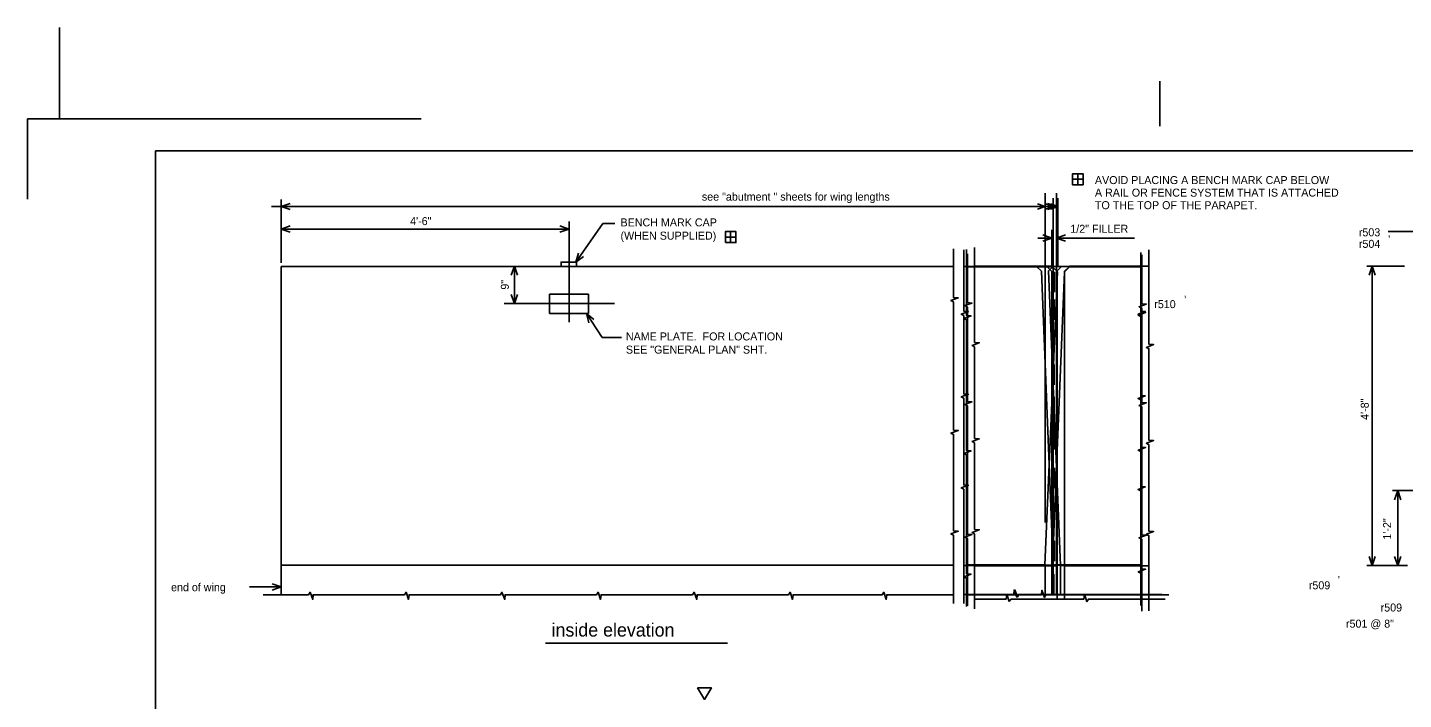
# Model space of a CAD drawing. Extents: x -81 to -44.8, y 85.9 to 111.1.
# Drawn here: x -79.8 to -58.31, y 100.62 to 111.12 of the extents above; entities that cross this region are included whole.
import ezdxf

# ---------------------------------------------------------------- set-up
doc = ezdxf.new("R2010")
doc.units = 0
for name, color, linetype in [('Default', 7, 'Continuous'), ('Level 1', 7, 'Continuous'), ('Level 12', 7, 'Continuous'), ('Level 13', 7, 'Continuous'), ('Level 14', 7, 'Continuous'), ('Level 15', 7, 'Continuous'), ('Level 16', 7, 'Continuous'), ('Level 2', 7, 'Continuous'), ('Level 37', 7, 'Continuous'), ('Level 5', 7, 'Continuous'), ('Level 9', 7, 'Continuous')]:
    doc.layers.add(name, color=color, linetype=linetype)

msp = doc.modelspace()

# ---------------------------------------------------------------- linework, layer by layer
at = {"layer": 'Default'}
msp.add_line((-57.819, 107.932), (-58.544, 107.932), dxfattribs=at)
at = {"layer": 'Level 1'}
for p, q in [((-73.646, 109.692), (-79.797, 109.692)), ((-79.797, 109.692), (-79.797, 108.439)), ((-77.797, 88.192), (-77.797, 109.192)), ((-46.422, 109.192), (-77.797, 109.192)), ((-58.289, 107.393), (-58.878, 107.393)), ((-58.795, 102.716), (-58.795, 107.393)), ((-57.703, 103.885), (-58.479, 103.885)), ((-58.395, 102.716), (-58.395, 103.885)), ((-58.243, 102.716), (-58.878, 102.716)), ((-58.475, 102.716), (-58.312, 102.716))]:
    msp.add_line(p, q, dxfattribs=at)
at = {"layer": 'Level 12'}
for p, q in [((-75.837, 108.323), (-63.724, 108.323)), ((-63.724, 107.33), (-63.724, 108.531)), ((-63.796, 107.363), (-63.796, 107.958)), ((-64.019, 107.83), (-63.796, 107.83)), ((-63.723, 107.83), (-62.508, 107.83)), ((-65.121, 107.387), (-63.876, 107.387)), ((-63.796, 107.307), (-63.876, 107.387)), ((-63.797, 107.308), (-63.797, 102.258)), ((-63.757, 107.3), (-63.757, 106.983)), ((-63.724, 107.306), (-63.724, 102.258)), ((-63.723, 107.307), (-63.647, 107.384)), ((-63.647, 107.387), (-62.405, 107.387)), ((-63.763, 106.868), (-63.763, 106.551)), ((-63.763, 106.362), (-63.763, 106.045)), ((-63.763, 105.855), (-63.763, 105.539)), ((-63.763, 105.349), (-63.763, 105.032)), ((-63.763, 104.842), (-63.763, 104.526)), ((-63.758, 104.243), (-63.758, 103.926)), ((-63.768, 103.696), (-63.768, 103.379)), ((-63.758, 103.101), (-63.758, 102.785)), ((-65.122, 102.72), (-63.797, 102.72)), ((-63.768, 102.58), (-63.768, 102.264)), ((-63.724, 102.72), (-62.406, 102.72))]:
    msp.add_line(p, q, dxfattribs=at)
for points in [[(-75.697, 108.275), (-75.837, 108.323), (-75.697, 108.372)], [(-63.865, 108.372), (-63.724, 108.323), (-63.865, 108.275)], [(-63.937, 107.878), (-63.796, 107.83), (-63.937, 107.781)], [(-63.582, 107.781), (-63.723, 107.83), (-63.582, 107.878)], [(-65.129, 105.733), (-65.129, 106.552), (-65.17, 106.573), (-65.058, 106.615), (-65.129, 106.62), (-65.129, 107.652)], [(-62.406, 105.785), (-62.406, 106.603), (-62.447, 106.625), (-62.335, 106.666), (-62.406, 106.672), (-62.406, 107.605)], [(-62.406, 103.675), (-62.406, 104.494), (-62.447, 104.515), (-62.335, 104.557), (-62.406, 104.562), (-62.406, 105.785)], [(-65.129, 103.623), (-65.129, 104.442), (-65.17, 104.463), (-65.058, 104.505), (-65.129, 104.511), (-65.129, 105.733)], [(-65.129, 102.078), (-65.129, 102.516), (-65.17, 102.538), (-65.058, 102.579), (-65.129, 102.585), (-65.129, 103.71)], [(-62.406, 102.094), (-62.406, 102.594), (-62.447, 102.615), (-62.335, 102.657), (-62.406, 102.663), (-62.406, 103.788)], [(-61.973, 102.258), (-63.891, 102.258), (-63.913, 102.217), (-63.954, 102.329), (-63.96, 102.258), (-65.129, 102.258)]]:
    msp.add_lwpolyline(points, dxfattribs=at)
at = {"layer": 'Level 13'}
for p, q in [((-75.983, 108.323), (-63.702, 108.323)), ((-63.702, 108.452), (-63.702, 107.402)), ((-65.004, 107.391), (-63.792, 107.391)), ((-63.715, 107.311), (-63.792, 107.387)), ((-63.715, 107.311), (-63.715, 102.192)), ((-63.6, 107.311), (-63.524, 107.387)), ((-63.6, 107.311), (-63.6, 102.192)), ((-63.524, 107.391), (-62.281, 107.391)), ((-65.004, 102.711), (-63.715, 102.711)), ((-63.6, 102.711), (-62.281, 102.711)), ((-64.509, 102.192), (-65.004, 102.192)), ((-64.503, 102.263), (-64.509, 102.192)), ((-64.462, 102.151), (-64.503, 102.263)), ((-64.44, 102.192), (-64.462, 102.151)), ((-63.889, 102.192), (-64.44, 102.192))]:
    msp.add_line(p, q, dxfattribs=at)
for points in [[(-63.821, 108.365), (-63.702, 108.323), (-63.821, 108.282)], [(-65.004, 105.579), (-65.004, 106.13), (-65.044, 106.152), (-64.933, 106.194), (-65.004, 106.199), (-65.004, 107.682)], [(-62.281, 105.551), (-62.281, 106.102), (-62.321, 106.123), (-62.21, 106.165), (-62.281, 106.171), (-62.281, 107.646)], [(-65.004, 104.08), (-65.004, 104.631), (-65.044, 104.653), (-64.933, 104.694), (-65.004, 104.7), (-65.004, 105.579)], [(-65.004, 104.08), (-65.004, 104.631), (-65.044, 104.653), (-64.933, 104.694), (-65.004, 104.7), (-65.004, 105.579)], [(-62.281, 104.051), (-62.281, 104.602), (-62.321, 104.624), (-62.21, 104.666), (-62.281, 104.671), (-62.281, 105.551)], [(-62.281, 104.051), (-62.281, 104.602), (-62.321, 104.624), (-62.21, 104.666), (-62.281, 104.671), (-62.281, 105.551)], [(-65.004, 102.038), (-65.004, 103.21), (-65.044, 103.232), (-64.933, 103.273), (-65.004, 103.279), (-65.004, 104.158)], [(-65.004, 102.038), (-65.004, 103.21), (-65.044, 103.232), (-64.933, 103.273), (-65.004, 103.279), (-65.004, 104.158)], [(-62.281, 102.01), (-62.281, 103.181), (-62.321, 103.203), (-62.21, 103.245), (-62.281, 103.25), (-62.281, 104.13)], [(-62.281, 102.01), (-62.281, 103.181), (-62.321, 103.203), (-62.21, 103.245), (-62.281, 103.25), (-62.281, 104.13)], [(-62.028, 102.192), (-63.227, 102.192), (-63.249, 102.151), (-63.29, 102.263), (-63.296, 102.192), (-64.175, 102.192)]]:
    msp.add_lwpolyline(points, dxfattribs=at)
at = {"layer": 'Level 14'}
for p, q in [((-75.837, 108.323), (-63.776, 108.323)), ((-63.776, 103.014), (-63.776, 108.452)), ((-65.173, 107.386), (-64.036, 107.388)), ((-63.962, 107.315), (-64.036, 107.388)), ((-63.776, 102.716), (-63.962, 107.315)), ((-63.848, 107.317), (-63.776, 107.388)), ((-63.661, 102.716), (-63.848, 107.317)), ((-63.776, 107.388), (-62.409, 107.386)), ((-65.173, 102.716), (-63.776, 102.716)), ((-63.776, 102.264), (-63.776, 102.716)), ((-63.661, 102.264), (-63.661, 102.716)), ((-63.661, 102.716), (-62.409, 102.716))]:
    msp.add_line(p, q, dxfattribs=at)
for points in [[(-63.896, 108.365), (-63.776, 108.323), (-63.896, 108.282)], [(-65.173, 106.069), (-65.173, 106.62), (-65.214, 106.641), (-65.102, 106.683), (-65.173, 106.689), (-65.173, 107.648)], [(-62.409, 106.069), (-62.409, 106.62), (-62.45, 106.641), (-62.338, 106.683), (-62.409, 106.689), (-62.409, 107.595)], [(-65.173, 104.776), (-65.173, 105.327), (-65.214, 105.349), (-65.102, 105.39), (-65.173, 105.396), (-65.173, 106.069)], [(-62.409, 104.75), (-62.409, 105.301), (-62.45, 105.323), (-62.338, 105.365), (-62.409, 105.371), (-62.409, 106.069)], [(-65.173, 102.124), (-65.173, 103.906), (-65.214, 103.928), (-65.102, 103.969), (-65.173, 103.975), (-65.173, 104.855)], [(-62.409, 102.091), (-62.409, 103.88), (-62.45, 103.902), (-62.338, 103.944), (-62.409, 103.95), (-62.409, 104.829)], [(-62.203, 102.264), (-64.314, 102.264), (-64.336, 102.223), (-64.377, 102.335), (-64.383, 102.264), (-65.173, 102.264)]]:
    msp.add_lwpolyline(points, dxfattribs=at)
at = {"layer": 'Level 15'}
for p, q in [((-63.901, 108.533), (-63.901, 103.385)), ((-75.985, 108.323), (-63.901, 108.323)), ((-65.105, 107.379), (-63.792, 107.382)), ((-63.906, 102.724), (-63.712, 107.302)), ((-63.712, 107.302), (-63.792, 107.382)), ((-63.786, 102.724), (-63.6, 107.303)), ((-63.6, 107.303), (-63.523, 107.38)), ((-63.523, 107.38), (-62.394, 107.379)), ((-65.117, 102.724), (-63.901, 102.724)), ((-63.901, 102.264), (-63.901, 102.724)), ((-63.786, 102.264), (-63.786, 102.724)), ((-63.786, 102.724), (-62.394, 102.724))]:
    msp.add_line(p, q, dxfattribs=at)
for points in [[(-64.021, 108.365), (-63.901, 108.323), (-64.021, 108.282)], [(-65.117, 106.04), (-65.117, 106.753), (-65.158, 106.774), (-65.046, 106.815), (-65.117, 106.821), (-65.117, 107.585)], [(-62.394, 106.024), (-62.394, 106.736), (-62.435, 106.758), (-62.323, 106.799), (-62.394, 106.805), (-62.394, 107.568)], [(-65.117, 104.496), (-65.117, 105.208), (-65.158, 105.23), (-65.046, 105.271), (-65.117, 105.277), (-65.117, 106.04)], [(-62.394, 104.482), (-62.394, 105.194), (-62.435, 105.216), (-62.323, 105.257), (-62.394, 105.263), (-62.394, 106.024)], [(-65.117, 102.086), (-65.117, 103.139), (-65.158, 103.16), (-65.046, 103.202), (-65.117, 103.207), (-65.117, 104.489)], [(-62.394, 102.002), (-62.394, 103.125), (-62.435, 103.146), (-62.323, 103.188), (-62.394, 103.194), (-62.394, 104.476)], [(-62.079, 102.264), (-64.325, 102.264), (-64.347, 102.223), (-64.388, 102.335), (-64.394, 102.264), (-65.117, 102.264)]]:
    msp.add_lwpolyline(points, dxfattribs=at)
at = {"layer": 'Level 2'}
msp.add_line((-79.297, 109.692), (-79.297, 111.118), dxfattribs=at)
for points in [[(-58.844, 107.252), (-58.795, 107.393), (-58.746, 107.252)], [(-58.444, 103.744), (-58.395, 103.885), (-58.347, 103.744)], [(-58.746, 102.856), (-58.795, 102.716), (-58.844, 102.856)], [(-58.347, 102.856), (-58.395, 102.716), (-58.444, 102.856)]]:
    msp.add_lwpolyline(points, dxfattribs=at)
at = {"layer": 'Level 37'}
msp.add_line((-62.109, 109.579), (-62.109, 110.279), dxfattribs=at)
at = {"layer": 'Level 5'}
for p, q in [((-75.837, 107.442), (-75.837, 108.431)), ((-75.837, 107.453), (-75.837, 108.413)), ((-75.837, 107.971), (-71.336, 107.971)), ((-71.336, 106.518), (-71.336, 108.086)), ((-70.809, 108.055), (-71.233, 107.453)), ((-70.809, 108.055), (-70.625, 108.055)), ((-65.332, 107.387), (-75.837, 107.387)), ((-75.837, 107.387), (-75.837, 102.72)), ((-72.193, 106.807), (-72.193, 107.39)), ((-71.644, 106.65), (-71.644, 106.956)), ((-71.644, 106.956), (-71.036, 106.956)), ((-71.036, 106.65), (-71.036, 106.956)), ((-72.35, 106.807), (-70.63, 106.807)), ((-71.644, 106.65), (-71.036, 106.65)), ((-71.068, 106.651), (-70.823, 106.278)), ((-70.823, 106.278), (-70.52, 106.278)), ((-75.837, 105.387), (-75.837, 105.356)), ((-65.332, 102.72), (-75.837, 102.72)), ((-75.837, 102.72), (-75.837, 102.258)), ((-76.33, 102.381), (-75.837, 102.381)), ((-71.705, 101.501), (-68.865, 101.501))]:
    msp.add_line(p, q, dxfattribs=at)
for points in [[(-63.475, 108.662), (-63.475, 108.835), (-63.311, 108.835), (-63.311, 108.662)], [(-63.475, 108.748), (-63.475, 108.835), (-63.393, 108.835), (-63.393, 108.748)], [(-63.393, 108.662), (-63.393, 108.748), (-63.311, 108.748), (-63.311, 108.662)], [(-68.897, 107.76), (-68.897, 107.932), (-68.733, 107.932), (-68.733, 107.76)], [(-68.897, 107.846), (-68.897, 107.932), (-68.815, 107.932), (-68.815, 107.846)], [(-68.815, 107.76), (-68.815, 107.846), (-68.733, 107.846), (-68.733, 107.76)], [(-71.463, 107.386), (-71.223, 107.386), (-71.223, 107.455), (-71.463, 107.455)], [(-69.334, 100.805), (-69.114, 100.805), (-69.224, 100.624)]]:
    msp.add_lwpolyline(points, close=True, dxfattribs=at)
for points in [[(-75.697, 107.922), (-75.837, 107.971), (-75.697, 108.02)], [(-71.485, 108.02), (-71.344, 107.971), (-71.485, 107.922)], [(-71.112, 107.54), (-71.233, 107.453), (-71.192, 107.596)], [(-65.332, 106.12), (-65.332, 106.832), (-65.373, 106.854), (-65.261, 106.895), (-65.332, 106.901), (-65.332, 107.662)], [(-72.242, 107.249), (-72.193, 107.39), (-72.145, 107.249)], [(-72.145, 106.948), (-72.193, 106.807), (-72.242, 106.948)], [(-71.032, 106.507), (-71.068, 106.651), (-70.95, 106.56)], [(-65.332, 104.23), (-65.332, 104.762), (-65.373, 104.784), (-65.261, 104.825), (-65.332, 104.831), (-65.332, 106.113)], [(-65.332, 102.124), (-65.332, 103.188), (-65.373, 103.21), (-65.261, 103.251), (-65.332, 103.257), (-65.332, 104.23)], [(-76.118, 102.258), (-75.406, 102.258), (-75.384, 102.299), (-75.343, 102.187), (-75.337, 102.258), (-74.619, 102.258)], [(-75.978, 102.43), (-75.837, 102.381), (-75.978, 102.332)], [(-74.619, 102.258), (-73.907, 102.258), (-73.885, 102.299), (-73.844, 102.187), (-73.838, 102.258), (-73.119, 102.258)], [(-73.119, 102.258), (-72.407, 102.258), (-72.386, 102.299), (-72.344, 102.187), (-72.338, 102.258), (-71.62, 102.258)], [(-71.62, 102.258), (-70.908, 102.258), (-70.886, 102.299), (-70.845, 102.187), (-70.839, 102.258), (-70.121, 102.258)], [(-70.121, 102.258), (-69.408, 102.258), (-69.387, 102.299), (-69.345, 102.187), (-69.34, 102.258), (-68.621, 102.258)], [(-68.115, 102.258), (-67.909, 102.258), (-67.887, 102.299), (-67.846, 102.187), (-67.84, 102.258), (-67.122, 102.258)], [(-67.158, 102.258), (-66.446, 102.258), (-66.424, 102.299), (-66.383, 102.187), (-66.377, 102.258), (-65.332, 102.258)], [(-68.621, 102.258), (-67.909, 102.258)]]:
    msp.add_lwpolyline(points, dxfattribs=at)

# ---------------------------------------------------------------- texts
at = {"layer": 'Default'}
msp.add_text('r503', height=0.125, dxfattribs=at).set_placement((-59.003, 107.857))
at = {"layer": 'Level 1'}
for s, p in [('4\'-8"', (-58.848, 104.99)), ('1\'-2"', (-58.499, 103.12))]:
    msp.add_text(s, height=0.125, rotation=90, dxfattribs=at).set_placement(p)
msp.add_text('r501 @ 8"', height=0.125, dxfattribs=at).set_placement((-59.204, 101.745))
at = {"layer": 'Level 12'}
msp.add_text('1/2" FILLER', height=0.125, dxfattribs=at).set_placement((-63.509, 107.912))
at = {"layer": 'Level 16'}
for s, p in [('r504', (-59.002, 107.677)), (',', (-58.553, 107.853))]:
    msp.add_text(s, height=0.125, dxfattribs=at).set_placement(p)
at = {"layer": 'Level 5'}
for s, height, p in [('AVOID PLACING A BENCH MARK CAP BELOW', 0.125, (-63.125, 108.673)), ('see "abutment " sheets for wing lengths', 0.125, (-69.264, 108.414)), ('A RAIL OR FENCE SYSTEM THAT IS ATTACHED', 0.125, (-63.125, 108.477)), ('TO THE TOP OF THE PARAPET.', 0.125, (-63.125, 108.281)), ('4\'-6"', 0.125, (-73.821, 108.032)), ('BENCH MARK CAP', 0.12503, (-70.535, 108.012)), ('(WHEN SUPPLIED)', 0.12503, (-70.535, 107.805)), ('NAME PLATE.  FOR LOCATION', 0.12503, (-70.451, 106.231)), ('SEE "GENERAL PLAN" SHT.', 0.12503, (-70.451, 106.025)), ('end of wing', 0.125, (-77.555, 102.314)), ('inside elevation', 0.20834, (-71.612, 101.606))]:
    msp.add_text(s, height=height, dxfattribs=at).set_placement(p)
msp.add_text('9"', height=0.125, rotation=90, dxfattribs=at).set_placement((-72.279, 107.024))
at = {"layer": 'Level 9'}
for s, p in [('r510', (-62.198, 106.735)), (',', (-61.738, 106.912)), (',', (-59.339, 102.533)), ('r509', (-59.784, 102.344)), ('r509', (-58.662, 101.997))]:
    msp.add_text(s, height=0.125, dxfattribs=at).set_placement(p)

doc.saveas('drawing.dxf')
